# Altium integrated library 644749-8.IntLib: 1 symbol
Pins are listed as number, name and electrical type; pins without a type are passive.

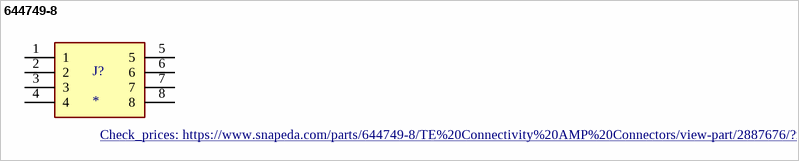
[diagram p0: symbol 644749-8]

## 644749-8
designator J?
8 Position Single Row 3.96 mm Through Hole Pin Header Plug Connector; MP: 644749-8; MF: TE Connectivity
footprint TE_644749-8
pins: 1, 2, 3, 4, 5, 6, 7, 8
